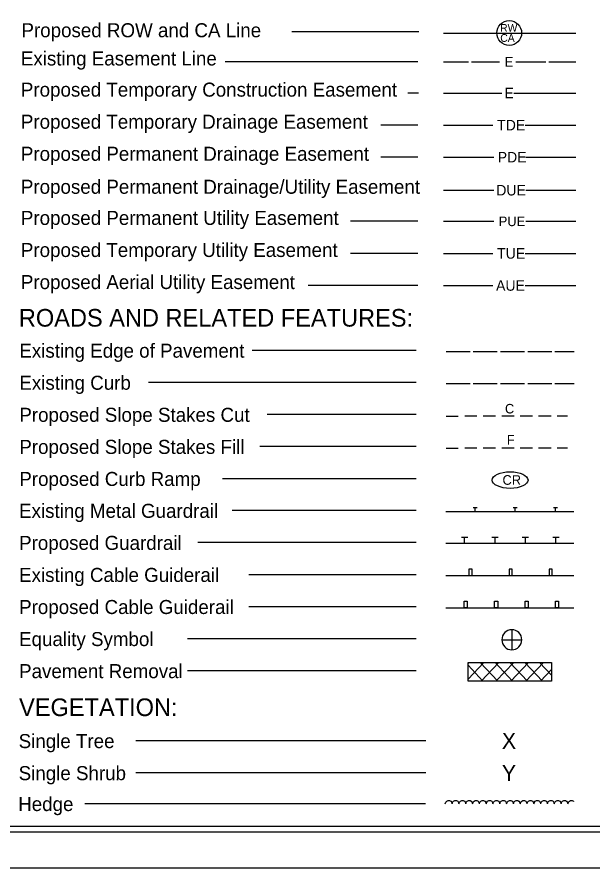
# Model space of a CAD drawing. Extents: x 1669394 to 1671078, y 697867 to 698967.
# Drawn here: x 1669956 to 1670316, y 697867 to 698398 of the extents above; entities that cross this region are included whole.
import ezdxf

# ---------------------------------------------------------------- set-up
doc = ezdxf.new("R2010")
doc.units = 0
for name, color, linetype in [('Prop Easement Permanent Drainage Utility', 7, 'Continuous'), ('Prop WCC CELL', 7, 'Continuous'), ('Sheet Cutting Line CELL', 7, 'Continuous'), ('Sheet Plot Border Inside CELL', 7, 'Continuous'), ('Sheet Plot Border Outside CELL', 7, 'Continuous'), ('Sheet Symbology CELL', 7, 'Continuous')]:
    doc.layers.add(name, color=color, linetype=linetype)

msp = doc.modelspace()

# ---------------------------------------------------------------- linework, layer by layer
at = {"layer": 'Prop Easement Permanent Drainage Utility'}
for p, q in [((1670222.68, 698289.78), (1670253.98, 698289.78)), ((1670273.98, 698289.78), (1670305.18, 698289.78))]:
    msp.add_line(p, q, dxfattribs=at)
at = {"layer": 'Prop WCC CELL'}
msp.add_ellipse((1670264.18, 698108.96), major_axis=(11.21, 0), ratio=0.462467, dxfattribs=at)
at = {"layer": 'Sheet Cutting Line CELL'}
msp.add_line((1669393.79, 697867.01), (1671077.79, 697867.01), dxfattribs=at)
at = {"layer": 'Sheet Plot Border Inside CELL'}
msp.add_lwpolyline([(1669406.79, 697889.46), (1671073.29, 697889.46), (1671073.29, 698944.56), (1669406.79, 698944.56)], close=True, dxfattribs=at)
at = {"layer": 'Sheet Plot Border Outside CELL'}
msp.add_lwpolyline([(1669393.79, 697867.01), (1671077.79, 697867.01), (1671077.79, 698967.01), (1669393.79, 698967.01)], close=True, dxfattribs=at)
at = {"layer": 'Sheet Symbology CELL'}
for p, q in [((1670207.28, 698388.43), (1670127.92, 698388.43)), ((1670222.69, 698387.66), (1670305.19, 698387.66)), ((1670206.65, 698369.81), (1670086.36, 698369.81)), ((1670222.68, 698369.81), (1670238.19, 698369.81)), ((1670240.19, 698369.81), (1670257.69, 698369.81)), ((1670267.69, 698369.81), (1670286.44, 698369.81)), ((1670288.44, 698369.81), (1670305.18, 698369.81)), ((1670207.03, 698350.36), (1670200.36, 698350.36)), ((1670222.68, 698350.36), (1670225.29, 698350.36)), ((1670225.29, 698350.36), (1670259.04, 698350.36)), ((1670266.54, 698350.36), (1670300.29, 698350.36)), ((1670300.29, 698350.36), (1670305.18, 698350.36)), ((1670206.65, 698330.36), (1670183.5, 698330.36)), ((1670222.68, 698330.36), (1670226.03, 698330.36)), ((1670226.03, 698330.36), (1670253.53, 698330.36)), ((1670273.53, 698330.36), (1670301.03, 698330.36)), ((1670301.03, 698330.36), (1670305.18, 698330.36)), ((1670206.65, 698310.36), (1670183.5, 698310.36)), ((1670222.68, 698310.36), (1670226.48, 698310.36)), ((1670226.48, 698310.36), (1670253.98, 698310.36)), ((1670273.98, 698310.36), (1670301.48, 698310.36)), ((1670301.48, 698310.36), (1670305.18, 698310.36)), ((1670206.65, 698270.35), (1670164.51, 698270.35)), ((1670222.68, 698270.35), (1670226.52, 698270.35)), ((1670226.52, 698270.35), (1670254.02, 698270.35)), ((1670274.02, 698270.35), (1670301.52, 698270.35)), ((1670301.52, 698270.35), (1670305.18, 698270.35)), ((1670206.65, 698250.35), (1670164.51, 698250.35)), ((1670222.68, 698250.35), (1670226.03, 698250.35)), ((1670226.03, 698250.35), (1670253.53, 698250.35)), ((1670273.53, 698250.35), (1670301.03, 698250.35)), ((1670301.03, 698250.35), (1670305.18, 698250.35)), ((1670206.65, 698230.35), (1670138.19, 698230.35)), ((1670222.68, 698230.35), (1670226.03, 698230.35)), ((1670226.03, 698230.35), (1670253.53, 698230.35)), ((1670273.53, 698230.35), (1670301.03, 698230.35)), ((1670301.03, 698230.35), (1670305.18, 698230.35)), ((1670205.69, 698189.83), (1670103.34, 698189.83)), ((1670224.22, 698189.25), (1670239.22, 698189.25)), ((1670241.22, 698189.25), (1670256.22, 698189.25)), ((1670258.22, 698189.25), (1670273.22, 698189.25)), ((1670275.22, 698189.25), (1670290.22, 698189.25)), ((1670292.22, 698189.25), (1670304.22, 698189.25)), ((1670205.69, 698169.83), (1670038.54, 698169.83)), ((1670224.22, 698169.25), (1670239.22, 698169.25)), ((1670241.22, 698169.25), (1670256.22, 698169.25)), ((1670258.22, 698169.25), (1670273.22, 698169.25)), ((1670275.22, 698169.25), (1670290.22, 698169.25)), ((1670292.22, 698169.25), (1670304.22, 698169.25)), ((1670205.69, 698149.83), (1670112.5, 698149.83)), ((1670224.22, 698148.78), (1670231.82, 698148.78)), ((1670243.52, 698148.78), (1670235.97, 698148.78)), ((1670255.02, 698148.78), (1670247.42, 698148.78)), ((1670266.77, 698148.78), (1670258.97, 698148.78)), ((1670278.22, 698148.78), (1670270.47, 698148.78)), ((1670289.77, 698148.78), (1670281.92, 698148.78)), ((1670300.07, 698148.78), (1670293.67, 698148.78)), ((1670205.69, 698129.83), (1670107.95, 698129.83)), ((1670224.22, 698128.78), (1670231.82, 698128.78)), ((1670243.52, 698128.78), (1670235.97, 698128.78)), ((1670255.02, 698128.78), (1670247.42, 698128.78)), ((1670266.77, 698128.78), (1670258.97, 698128.78)), ((1670278.22, 698128.78), (1670270.47, 698128.78)), ((1670289.77, 698128.78), (1670281.92, 698128.78)), ((1670300.07, 698128.78), (1670293.67, 698128.78)), ((1670205.69, 698109.83), (1670084.76, 698109.83)), ((1670205.53, 698089.94), (1670090.69, 698089.94)), ((1670224.06, 698089.37), (1670304.06, 698089.37)), ((1670241.2, 698091.87), (1670243.7, 698091.87)), ((1670242.45, 698089.37), (1670242.45, 698091.87)), ((1670266.2, 698091.87), (1670268.7, 698091.87)), ((1670267.45, 698089.37), (1670267.45, 698091.87)), ((1670291.2, 698091.87), (1670293.7, 698091.87)), ((1670292.45, 698089.37), (1670292.45, 698091.87)), ((1670233.79, 698073.32), (1670237.79, 698073.32)), ((1670235.79, 698069.37), (1670235.79, 698073.32)), ((1670252.79, 698073.32), (1670256.79, 698073.32)), ((1670254.79, 698069.37), (1670254.79, 698073.32)), ((1670271.79, 698073.32), (1670275.79, 698073.32)), ((1670273.79, 698069.37), (1670273.79, 698073.32)), ((1670290.79, 698073.32), (1670294.79, 698073.32)), ((1670292.79, 698069.37), (1670292.79, 698073.32)), ((1670205.53, 698069.94), (1670069.29, 698069.94)), ((1670304.06, 698069.37), (1670224.06, 698069.37)), ((1670205.53, 698049.94), (1670101.23, 698049.94)), ((1670224.06, 698049.37), (1670304.06, 698049.37)), ((1670205.53, 698029.94), (1670101.23, 698029.94)), ((1670224.06, 698029.37), (1670304.06, 698029.37)), ((1670265.29, 698015.61), (1670265.29, 698009.36)), ((1670205.53, 698009.94), (1670062.91, 698009.94)), ((1670259.04, 698009.36), (1670265.29, 698009.36)), ((1670265.29, 698009.36), (1670265.29, 698003.11)), ((1670265.29, 698009.36), (1670271.54, 698009.36)), ((1670238.01, 697995.23), (1670290.11, 697995.23)), ((1670238.01, 697983.53), (1670238.01, 697995.23)), ((1670238.01, 697994.63), (1670238.56, 697995.23)), ((1670238.01, 697984.68), (1670247.86, 697995.23)), ((1670256.56, 697983.53), (1670245.56, 697995.23)), ((1670246.16, 697983.53), (1670257.16, 697995.23)), ((1670265.81, 697983.53), (1670254.86, 697995.23)), ((1670255.41, 697983.53), (1670266.46, 697995.23)), ((1670275.11, 697983.53), (1670264.11, 697995.23)), ((1670264.71, 697983.53), (1670275.71, 697995.23)), ((1670284.41, 697983.53), (1670273.36, 697995.23)), ((1670274.01, 697983.53), (1670284.96, 697995.23)), ((1670290.11, 697987.28), (1670282.66, 697995.23)), ((1670290.11, 697995.23), (1670290.11, 697983.53)), ((1670205.53, 697989.94), (1670062.91, 697989.94)), ((1670247.26, 697983.53), (1670238.01, 697993.43)), ((1670283.26, 697983.53), (1670290.11, 697990.83)), ((1670290.11, 697983.53), (1670238.01, 697983.53)), ((1670211.67, 697946.3), (1670030.54, 697946.3)), ((1670211.67, 697926.3), (1670030.54, 697926.3)), ((1670224.69, 697908.64), (1670225.49, 697909.09)), ((1670225.49, 697909.09), (1670226.44, 697909.09)), ((1670226.44, 697909.09), (1670227.24, 697908.59)), ((1670228.94, 697908.64), (1670229.74, 697909.09)), ((1670229.74, 697909.09), (1670230.69, 697909.09)), ((1670230.69, 697909.09), (1670231.49, 697908.59)), ((1670233.19, 697908.64), (1670233.99, 697909.09)), ((1670233.99, 697909.09), (1670234.94, 697909.09)), ((1670234.94, 697909.09), (1670235.74, 697908.59)), ((1670237.44, 697908.64), (1670238.24, 697909.09)), ((1670238.24, 697909.09), (1670239.19, 697909.09)), ((1670239.19, 697909.09), (1670239.99, 697908.59)), ((1670241.69, 697908.64), (1670242.49, 697909.09)), ((1670242.49, 697909.09), (1670243.44, 697909.09)), ((1670243.44, 697909.09), (1670244.24, 697908.59)), ((1670245.94, 697908.64), (1670246.74, 697909.09)), ((1670246.74, 697909.09), (1670247.69, 697909.09)), ((1670247.69, 697909.09), (1670248.49, 697908.59)), ((1670250.19, 697908.64), (1670250.99, 697909.09)), ((1670250.99, 697909.09), (1670251.94, 697909.09)), ((1670251.94, 697909.09), (1670252.74, 697908.59)), ((1670254.44, 697908.64), (1670255.24, 697909.09)), ((1670255.24, 697909.09), (1670256.19, 697909.09)), ((1670256.19, 697909.09), (1670256.99, 697908.59)), ((1670258.69, 697908.64), (1670259.49, 697909.09)), ((1670259.49, 697909.09), (1670260.44, 697909.09)), ((1670260.44, 697909.09), (1670261.24, 697908.59)), ((1670262.94, 697908.64), (1670263.74, 697909.09)), ((1670263.74, 697909.09), (1670264.69, 697909.09)), ((1670264.69, 697909.09), (1670265.49, 697908.59)), ((1670267.19, 697908.64), (1670267.99, 697909.09)), ((1670267.99, 697909.09), (1670268.94, 697909.09)), ((1670268.94, 697909.09), (1670269.74, 697908.59)), ((1670271.44, 697908.64), (1670272.24, 697909.09)), ((1670272.24, 697909.09), (1670273.19, 697909.09)), ((1670273.19, 697909.09), (1670273.99, 697908.59)), ((1670275.69, 697908.64), (1670276.49, 697909.09)), ((1670276.49, 697909.09), (1670277.44, 697909.09)), ((1670277.44, 697909.09), (1670278.24, 697908.59)), ((1670279.94, 697908.64), (1670280.74, 697909.09)), ((1670280.74, 697909.09), (1670281.69, 697909.09)), ((1670281.69, 697909.09), (1670282.49, 697908.59)), ((1670284.19, 697908.64), (1670284.99, 697909.09)), ((1670284.99, 697909.09), (1670285.94, 697909.09)), ((1670285.94, 697909.09), (1670286.74, 697908.59)), ((1670288.44, 697908.64), (1670289.24, 697909.09)), ((1670289.24, 697909.09), (1670290.19, 697909.09)), ((1670290.19, 697909.09), (1670290.99, 697908.59)), ((1670292.69, 697908.64), (1670293.49, 697909.09)), ((1670293.49, 697909.09), (1670294.44, 697909.09)), ((1670294.44, 697909.09), (1670295.24, 697908.59)), ((1670296.94, 697908.64), (1670297.74, 697909.09)), ((1670297.74, 697909.09), (1670298.69, 697909.09)), ((1670298.69, 697909.09), (1670299.49, 697908.59)), ((1670301.19, 697908.64), (1670301.99, 697909.09)), ((1670301.99, 697909.09), (1670302.94, 697909.09)), ((1670302.94, 697909.09), (1670303.74, 697908.59)), ((1670211.4, 697907.04), (1669998.71, 697907.04)), ((1670223.79, 697907.04), (1670224.09, 697907.99)), ((1670224.09, 697907.99), (1670224.69, 697908.64)), ((1670227.24, 697908.59), (1670227.79, 697907.94)), ((1670227.79, 697907.94), (1670227.99, 697907.09)), ((1670228.04, 697907.04), (1670228.34, 697907.99)), ((1670228.34, 697907.99), (1670228.94, 697908.64)), ((1670231.49, 697908.59), (1670232.04, 697907.94)), ((1670232.04, 697907.94), (1670232.24, 697907.09)), ((1670232.29, 697907.04), (1670232.59, 697907.99)), ((1670232.59, 697907.99), (1670233.19, 697908.64)), ((1670235.74, 697908.59), (1670236.29, 697907.94)), ((1670236.29, 697907.94), (1670236.49, 697907.09)), ((1670236.54, 697907.04), (1670236.84, 697907.99)), ((1670236.84, 697907.99), (1670237.44, 697908.64)), ((1670239.99, 697908.59), (1670240.54, 697907.94)), ((1670240.54, 697907.94), (1670240.74, 697907.09)), ((1670240.79, 697907.04), (1670241.09, 697907.99)), ((1670241.09, 697907.99), (1670241.69, 697908.64)), ((1670244.24, 697908.59), (1670244.79, 697907.94)), ((1670244.79, 697907.94), (1670244.99, 697907.09)), ((1670245.04, 697907.04), (1670245.34, 697907.99)), ((1670245.34, 697907.99), (1670245.94, 697908.64)), ((1670248.49, 697908.59), (1670249.04, 697907.94)), ((1670249.04, 697907.94), (1670249.24, 697907.09)), ((1670249.29, 697907.04), (1670249.59, 697907.99)), ((1670249.59, 697907.99), (1670250.19, 697908.64)), ((1670252.74, 697908.59), (1670253.29, 697907.94)), ((1670253.29, 697907.94), (1670253.49, 697907.09)), ((1670253.54, 697907.04), (1670253.84, 697907.99)), ((1670253.84, 697907.99), (1670254.44, 697908.64)), ((1670256.99, 697908.59), (1670257.54, 697907.94)), ((1670257.54, 697907.94), (1670257.74, 697907.09)), ((1670257.79, 697907.04), (1670258.09, 697907.99)), ((1670258.09, 697907.99), (1670258.69, 697908.64)), ((1670261.24, 697908.59), (1670261.79, 697907.94)), ((1670261.79, 697907.94), (1670261.99, 697907.09)), ((1670262.04, 697907.04), (1670262.34, 697907.99)), ((1670262.34, 697907.99), (1670262.94, 697908.64)), ((1670265.49, 697908.59), (1670266.04, 697907.94)), ((1670266.04, 697907.94), (1670266.24, 697907.09)), ((1670266.29, 697907.04), (1670266.59, 697907.99)), ((1670266.59, 697907.99), (1670267.19, 697908.64)), ((1670269.74, 697908.59), (1670270.29, 697907.94)), ((1670270.29, 697907.94), (1670270.49, 697907.09)), ((1670270.54, 697907.04), (1670270.84, 697907.99)), ((1670270.84, 697907.99), (1670271.44, 697908.64)), ((1670273.99, 697908.59), (1670274.54, 697907.94)), ((1670274.54, 697907.94), (1670274.74, 697907.09)), ((1670274.79, 697907.04), (1670275.09, 697907.99)), ((1670275.09, 697907.99), (1670275.69, 697908.64)), ((1670278.24, 697908.59), (1670278.79, 697907.94)), ((1670278.79, 697907.94), (1670278.99, 697907.09)), ((1670279.04, 697907.04), (1670279.34, 697907.99)), ((1670279.34, 697907.99), (1670279.94, 697908.64)), ((1670282.49, 697908.59), (1670283.04, 697907.94)), ((1670283.04, 697907.94), (1670283.24, 697907.09)), ((1670283.29, 697907.04), (1670283.59, 697907.99)), ((1670283.59, 697907.99), (1670284.19, 697908.64)), ((1670286.74, 697908.59), (1670287.29, 697907.94)), ((1670287.29, 697907.94), (1670287.49, 697907.09)), ((1670287.54, 697907.04), (1670287.84, 697907.99)), ((1670287.84, 697907.99), (1670288.44, 697908.64)), ((1670290.99, 697908.59), (1670291.54, 697907.94)), ((1670291.54, 697907.94), (1670291.74, 697907.09)), ((1670291.79, 697907.04), (1670292.09, 697907.99)), ((1670292.09, 697907.99), (1670292.69, 697908.64)), ((1670295.24, 697908.59), (1670295.79, 697907.94)), ((1670295.79, 697907.94), (1670295.99, 697907.09)), ((1670296.04, 697907.04), (1670296.34, 697907.99)), ((1670296.34, 697907.99), (1670296.94, 697908.64)), ((1670299.49, 697908.59), (1670300.04, 697907.94)), ((1670300.04, 697907.94), (1670300.24, 697907.09)), ((1670300.29, 697907.04), (1670300.59, 697907.99)), ((1670300.59, 697907.99), (1670301.19, 697908.64)), ((1670303.74, 697908.59), (1670303.79, 697908.54))]:
    msp.add_line(p, q, dxfattribs=at)
for points in [[(1671060.79, 698942.01), (1669560.79, 698942.01), (1669560.79, 697893.03), (1671060.79, 697893.03)], [(1670238.54, 698049.37), (1670240.54, 698049.37), (1670240.54, 698053.37), (1670238.54, 698053.37)], [(1670263.54, 698049.37), (1670265.54, 698049.37), (1670265.54, 698053.37), (1670263.54, 698053.37)], [(1670288.54, 698049.37), (1670290.54, 698049.37), (1670290.54, 698053.37), (1670288.54, 698053.37)], [(1670235.52, 698033.37), (1670237.52, 698033.37), (1670237.52, 698029.37), (1670235.52, 698029.37)], [(1670254.52, 698033.37), (1670256.52, 698033.37), (1670256.52, 698029.37), (1670254.52, 698029.37)], [(1670273.52, 698033.37), (1670275.52, 698033.37), (1670275.52, 698029.37), (1670273.52, 698029.37)], [(1670292.52, 698033.37), (1670294.52, 698033.37), (1670294.52, 698029.37), (1670292.52, 698029.37)]]:
    msp.add_lwpolyline(points, close=True, dxfattribs=at)
msp.add_circle((1670263.68, 698387.81), 7.72, dxfattribs=at)
for start, end in [(89.9944, 179.9989), (359.9944, 89.9989), (179.9944, 269.9989), (269.9944, 359.9989)]:
    msp.add_arc((1670265.29, 698009.36), 6.25, start, end, dxfattribs=at)

# ---------------------------------------------------------------- texts
at = {"layer": 'Prop Easement Permanent Drainage Utility'}
msp.add_text('DUE', height=6.55, dxfattribs=at).set_placement((1670255.57, 698286.48))
at = {"layer": 'Prop WCC CELL'}
msp.add_text('CR', height=6, dxfattribs=at).set_placement((1670259.47, 698106.01))
at = {"layer": 'Sheet Symbology CELL'}
for s, height, p in [('Proposed ROW and CA Line', 8.75, (1669959.26, 698385.15)), ('RW', 4.838, (1670258, 698388.58)), ('CA', 4.838, (1670258.07, 698382.29)), ('Existing Easement Line', 8.75, (1669958.9, 698367.55)), ('E', 6, (1670260.89, 698366.81)), ('Proposed Temporary Construction Easement', 8.75, (1669958.9, 698348.1)), ('E', 6.55, (1670260.64, 698347.06)), ('Proposed Temporary Drainage Easement', 8.75, (1669958.9, 698328.1)), ('TDE', 6.55, (1670256.13, 698327.06)), ('Proposed Permanent Drainage Easement', 8.75, (1669958.9, 698308.1)), ('PDE', 6.55, (1670256.48, 698307.06)), ('Proposed Permanent Drainage/Utility Easement', 8.75, (1669958.9, 698287.52)), ('Proposed Permanent Utility Easement', 8.75, (1669958.9, 698268.09)), ('PUE', 6, (1670257.12, 698267.35)), ('Proposed Temporary Utility Easement', 8.75, (1669958.9, 698248.09)), ('TUE', 6.55, (1670256.11, 698247.05)), ('Proposed Aerial Utility Easement', 8.75, (1669958.9, 698228.09)), ('AUE', 6.55, (1670255.45, 698227.05)), ('ROADS AND RELATED FEATURES:', 11, (1669957.64, 698204.67)), ('Existing Edge of Pavement', 8.75, (1669957.94, 698185.28)), ('Existing Curb', 8.75, (1669957.94, 698165.28)), ('Proposed Slope Stakes Cut', 8.75, (1669957.94, 698145.28)), ('C', 5.93, (1670261.02, 698150.51)), ('F', 5.93, (1670262.22, 698131.14)), ('Proposed Slope Stakes Fill', 8.75, (1669957.94, 698125.28)), ('Proposed Curb Ramp', 8.75, (1669957.94, 698105.28)), ('Existing Metal Guardrail', 8.75, (1669957.78, 698085.39)), ('Proposed Guardrail', 8.75, (1669957.79, 698065.41)), ('Existing Cable Guiderail', 8.75, (1669957.79, 698045.41)), ('Proposed Cable Guiderail', 8.75, (1669957.79, 698025.41)), ('Equality Symbol', 8.75, (1669957.79, 698005.41)), ('Pavement Removal', 8.75, (1669957.79, 697985.41)), ('VEGETATION:', 11, (1669957.78, 697961.75)), ('X', 10, (1670259.06, 697941.3)), ('Single Tree', 8.75, (1669957.51, 697941.78)), ('Single Shrub', 8.75, (1669957.51, 697921.78)), ('Y', 10, (1670259.06, 697921.3)), ('Hedge', 8.75, (1669957.24, 697902.52))]:
    msp.add_text(s, height=height, dxfattribs=at).set_placement(p)

doc.saveas('drawing.dxf')
